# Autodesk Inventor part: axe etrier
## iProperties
Created: 2002-03
Part Number: axe etrier
Material: Par défaut
Document SubType Name: Modélisation
Designer: BAVERGE
Control State: 0
Master: False
Checked Out: False
Shininess: 20.0
Length Units: 11269
Angle Units: 11279
Time Units: 11290
Mass Units: 11283
Length Display Precision: 3
Angle Display Precision: 2
Density: 0.0
Volumn: 0.0
Area: 0.0
PropertySet Name: Model Information
Author: BAVERGE
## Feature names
1. Révolution1 [Revolution]
